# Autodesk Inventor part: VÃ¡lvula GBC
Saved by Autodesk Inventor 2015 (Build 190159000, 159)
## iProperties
Created: 2015-06
Part Number: VÃ¡lvula GBC
Material: Generic
Document SubType Name: Modeling
Designer: Franzi-CAD
Density: 1 g/cm^3
Appearance: Smooth - Yellow
Translation Standard: IGES 5.3
FileName: 1 Sistema de RefrigeraÃ§Ã£o Industrial - 3D v3
PreProcessor: AutoCAD 2015 - English
PostProcessor: Build: 160, Release: 2012 RTM - Date: Tue 03/01/2011
Sent Units: millimeter
Uncertainty: 0.01
Author: Franzi-CAD
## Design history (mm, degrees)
node "VÃ¡lvula GBC1"
  sketch "3D Sketch1"
node "1 Sistema de Refrigeração Industrial - 3D v3"
node "1 Sistema de Refrigeração Industrial - 3D v3_1"
node "1 Sistema de Refrigeração Industrial - 3D v3_2"
node "1 Sistema de Refrigeração Industrial - 3D v3_3"
node "1 Sistema de Refrigeração Industrial - 3D v3_4"
node "1 Sistema de Refrigeração Industrial - 3D v3_5"
node "1 Sistema de Refrigeração Industrial - 3D v3_6"
node "1 Sistema de Refrigeração Industrial - 3D v3_7"
node "1 Sistema de Refrigeração Industrial - 3D v3_8"
node "1 Sistema de Refrigeração Industrial - 3D v3_9"
node "1 Sistema de Refrigeração Industrial - 3D v3_10"
node "1 Sistema de Refrigeração Industrial - 3D v3_11"
node "1 Sistema de Refrigeração Industrial - 3D v3_12"
node "1 Sistema de Refrigeração Industrial - 3D v3_13"
node "1 Sistema de Refrigeração Industrial - 3D v3_14"
node "1 Sistema de Refrigeração Industrial - 3D v3_15"
node "1 Sistema de Refrigeração Industrial - 3D v3_16"
node "1 Sistema de Refrigeração Industrial - 3D v3_17"
node "1 Sistema de Refrigeração Industrial - 3D v3_18"
node "1 Sistema de Refrigeração Industrial - 3D v3_19"
node "1 Sistema de Refrigeração Industrial - 3D v3_20"
node "1 Sistema de Refrigeração Industrial - 3D v3_21"
node "1 Sistema de Refrigeração Industrial - 3D v3_22"
node "1 Sistema de Refrigeração Industrial - 3D v3_23"
node "1 Sistema de Refrigeração Industrial - 3D v3_24"
node "1 Sistema de Refrigeração Industrial - 3D v3_25"
node "1 Sistema de Refrigeração Industrial - 3D v3_26"
node "1 Sistema de Refrigeração Industrial - 3D v3_27"
node "1 Sistema de Refrigeração Industrial - 3D v3_28"
node "1 Sistema de Refrigeração Industrial - 3D v3_29"
node "1 Sistema de Refrigeração Industrial - 3D v3_30"
node "1 Sistema de Refrigeração Industrial - 3D v3_31"
node "1 Sistema de Refrigeração Industrial - 3D v3_32"
node "1 Sistema de Refrigeração Industrial - 3D v3_33"
node "1 Sistema de Refrigeração Industrial - 3D v3_34"
node "1 Sistema de Refrigeração Industrial - 3D v3_35"
node "1 Sistema de Refrigeração Industrial - 3D v3_36"
node "1 Sistema de Refrigeração Industrial - 3D v3_37"
node "1 Sistema de Refrigeração Industrial - 3D v3_38"
node "1 Sistema de Refrigeração Industrial - 3D v3_39"
node "1 Sistema de Refrigeração Industrial - 3D v3_40"
node "1 Sistema de Refrigeração Industrial - 3D v3_41"
node "Base1"
node "Base2"
node "Base3"
node "Base4"
node "Base5"
node "Base6"
node "Base7"
node "Base8"
node "Base9"
node "Base10"
node "Base11"
node "Base12"
node "Base13"
node "Base14"
node "Base15"
node "Base16"
node "Base17"
node "Base18"
node "Base19"
node "Base20"
node "Base21"
node "Base22"
node "Base23"
node "Base24"
node "Base25"
node "Base26"
node "Base27"
node "Base28"
node "Base29"
node "Base30"
node "Base31"
node "Base32"
node "Base33"
node "Base34"
node "Base35"
node "Base36"
node "Base37"
node "Base38"
node "Base39"
node "Base40"
node "Base41"
node "Base42"
